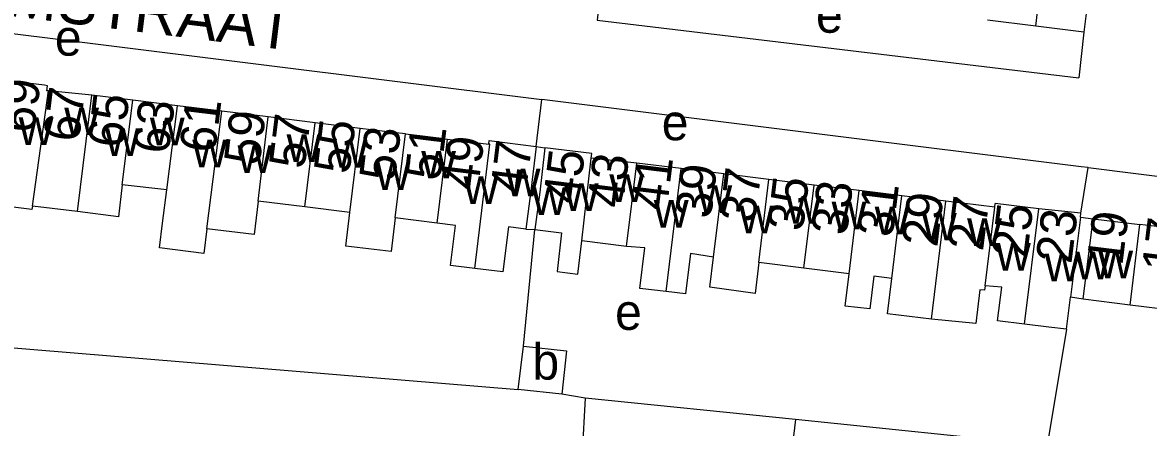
# Model space of a CAD drawing. Extents: x 157569 to 159501, y 382907 to 384670.
# Drawn here: x 158378.5 to 158503.7, y 383217.2 to 383262.2 of the extents above; entities that cross this region are included whole.
import ezdxf

# ---------------------------------------------------------------- set-up
doc = ezdxf.new("R2010")
doc.units = 0
for name, color, linetype in [('BLT_Basislijn', 7, 'Continuous'), ('BLT_Bebouwing', 7, 'Continuous'), ('BLT_Centroide', 7, 'Continuous'), ('BLT_Huisnummer', 7, 'Continuous'), ('BLT_Huisnummer_ tussenligend', 7, 'Continuous'), ('BLT_Onderdoorgang_en_onderverdeling', 7, 'Continuous'), ('BLT_Onderverdeling_panden', 7, 'Continuous'), ('BLT_Straatnaam', 7, 'Continuous')]:
    doc.layers.add(name, color=color, linetype=linetype)

msp = doc.modelspace()

# ---------------------------------------------------------------- linework, layer by layer
at = {"layer": 'BLT_Basislijn'}
for p, q in [((158496.49, 383261.17), (158495.91, 383256.08)), ((158435.58, 383248.43), (158436.22, 383253.68)), ((158496.15, 383241.01), (158496.96, 383246.09)), ((158434.19, 383226.22), (158435.43, 383239.19)), ((158494.57, 383228.1), (158492.39, 383215.18)), ((158367.29, 383226.88), (158433.59, 383221.41)), ((158441.03, 383220.43), (158438.43, 383220.88)), ((158441.03, 383220.43), (158439.9, 383199.74)), ((158464.44, 383218.06), (158441.03, 383220.43)), ((158492.39, 383215.18), (158464.44, 383218.06))]:
    msp.add_line(p, q, dxfattribs=at)
for points in [[(158442.95, 383267.73), (158442.38, 383262.5), (158495.91, 383256.08)], [(158339.59, 383265.74), (158436.22, 383253.68)], [(158496.96, 383246.09), (158496.17, 383246.19), (158436.22, 383253.68)], [(158496.96, 383246.09), (158554.1, 383238.91), (158555.85, 383237.47)], [(158464.44, 383218.06), (158463.94, 383214.05), (158463.22, 383193.67)]]:
    msp.add_lwpolyline(points, dxfattribs=at)
at = {"layer": 'BLT_Bebouwing'}
for p, q in [((158497.58, 383270.14), (158496.49, 383261.17)), ((158491.14, 383261.83), (158485.78, 383262.48)), ((158496.49, 383261.17), (158491.14, 383261.83)), ((158380.92, 383255.24), (158376.31, 383255.8)), ((158386.19, 383254.14), (158381.36, 383254.61)), ((158390.73, 383253.58), (158386.19, 383254.14)), ((158395.72, 383252.96), (158390.73, 383253.58)), ((158400.65, 383252.35), (158395.72, 383252.96)), ((158405.79, 383251.72), (158400.65, 383252.35)), ((158411.01, 383251.07), (158405.79, 383251.72)), ((158416.03, 383250.45), (158411.01, 383251.07)), ((158421.06, 383249.83), (158425.72, 383249.26)), ((158425.72, 383249.26), (158430.33, 383248.69)), ((158435.58, 383248.43), (158436.55, 383248.3)), ((158446.78, 383246.57), (158441.7, 383247.15)), ((158451.7, 383245.97), (158446.78, 383246.57)), ((158456.45, 383245.39), (158451.7, 383245.97)), ((158461.47, 383244.77), (158456.45, 383245.39)), ((158394.53, 383243.6), (158389.57, 383244.18)), ((158466.49, 383244.15), (158461.47, 383244.77)), ((158471.51, 383243.54), (158466.49, 383244.15)), ((158476.25, 383242.93), (158471.51, 383243.54)), ((158481.13, 383242.34), (158476.25, 383242.93)), ((158384.6, 383241.19), (158379.58, 383241.8)), ((158409.86, 383241.72), (158404.67, 383242.36)), ((158414.89, 383241.11), (158409.86, 383241.72)), ((158486.58, 383241.69), (158481.13, 383242.34)), ((158486.58, 383241.69), (158486.63, 383242.11)), ((158491.47, 383241.52), (158486.63, 383242.11)), ((158496.15, 383241.01), (158491.47, 383241.52)), ((158424.58, 383239.92), (158419.91, 383240.49)), ((158496.1, 383240.57), (158496.15, 383241.01)), ((158497.52, 383240.39), (158502.71, 383239.76)), ((158434.45, 383239.25), (158435.43, 383239.19)), ((158508.37, 383239.07), (158502.71, 383239.76)), ((158465.36, 383234.9), (158460.33, 383235.52)), ((158470.38, 383234.29), (158465.36, 383234.9)), ((158494.57, 383228.1), (158495.01, 383231.68)), ((158501.62, 383230.8), (158496.42, 383231.44)), ((158507.02, 383230.14), (158501.62, 383230.8)), ((158433.59, 383221.41), (158434.19, 383226.22)), ((158438.43, 383220.88), (158433.59, 383221.41))]:
    msp.add_line(p, q, dxfattribs=at)
for points in [[(158381.36, 383254.61), (158381.19, 383254.63), (158381.26, 383255.2), (158380.92, 383255.24)], [(158421.06, 383249.83), (158419.68, 383250), (158416.03, 383250.45)], [(158430.33, 383248.69), (158430.37, 383249.1), (158435.58, 383248.43)], [(158441.7, 383247.15), (158441.76, 383247.66), (158436.55, 383248.3)], [(158379.58, 383241.8), (158379.53, 383241.43), (158374.76, 383242.01), (158375.25, 383246.36)], [(158389.57, 383244.18), (158389.14, 383240.63), (158384.6, 383241.19)], [(158398.98, 383239.28), (158398.63, 383236.53), (158393.71, 383237.16), (158394.06, 383239.89), (158394.53, 383243.6)], [(158404.67, 383242.36), (158404.22, 383238.64), (158398.98, 383239.28)], [(158419.91, 383240.49), (158419.45, 383236.74), (158414.42, 383237.36), (158414.89, 383241.11)], [(158428.77, 383234.87), (158426.07, 383235.2), (158426.61, 383239.63), (158424.58, 383239.92)], [(158496.1, 383240.57), (158497.52, 383240.39)], [(158434.45, 383239.25), (158432.51, 383239.49), (158431.9, 383234.49), (158428.77, 383234.87)], [(158435.43, 383239.19), (158438.42, 383238.82), (158437.92, 383234.53), (158440.24, 383234.25), (158440.68, 383237.93)], [(158445.65, 383237.32), (158440.68, 383237.93)], [(158450.03, 383232.3), (158447.11, 383232.65), (158447.67, 383237.15), (158445.65, 383237.32)], [(158455.31, 383236.14), (158452.73, 383236.52), (158452.18, 383232.03), (158450.03, 383232.3)], [(158460.33, 383235.52), (158459.94, 383232.1), (158454.88, 383232.78), (158455.31, 383236.14)], [(158475.13, 383233.77), (158473.13, 383234.02), (158472.68, 383230.39), (158469.94, 383230.69), (158470.38, 383234.29)], [(158479.53, 383229.22), (158474.65, 383229.81), (158475.13, 383233.77)], [(158485.5, 383232.95), (158485.44, 383232.44), (158484.92, 383232.49), (158484.46, 383228.73), (158479.53, 383229.22)], [(158489.89, 383228.67), (158486.89, 383229.04), (158487.35, 383232.79), (158485.5, 383232.95)], [(158496.42, 383231.44), (158495.01, 383231.68)], [(158494.57, 383228.1), (158492.58, 383228.34), (158489.89, 383228.67)], [(158434.19, 383226.22), (158438.96, 383225.7), (158438.43, 383220.88)]]:
    msp.add_lwpolyline(points, dxfattribs=at)
at = {"layer": 'BLT_Onderdoorgang_en_onderverdeling'}
msp.add_line((158496.42, 383231.44), (158497.52, 383240.39), dxfattribs=at)
for points in [[(158435.58, 383248.43), (158435.01, 383243.49), (158434.45, 383239.25)], [(158436.55, 383248.3), (158435.98, 383243.37), (158435.43, 383239.19)], [(158496.1, 383240.57), (158495.01, 383231.68)]]:
    msp.add_lwpolyline(points, dxfattribs=at)
at = {"layer": 'BLT_Onderverdeling_panden'}
for p, q in [((158491.14, 383261.83), (158492.23, 383270.8)), ((158379.58, 383241.8), (158381.36, 383254.61)), ((158384.6, 383241.19), (158386.19, 383254.14)), ((158389.57, 383244.18), (158390.73, 383253.58)), ((158394.53, 383243.6), (158395.72, 383252.96)), ((158398.98, 383239.28), (158400.65, 383252.35)), ((158404.67, 383242.36), (158405.79, 383251.72)), ((158409.86, 383241.72), (158411.01, 383251.07)), ((158414.89, 383241.11), (158416.03, 383250.45)), ((158419.91, 383240.49), (158421.06, 383249.83)), ((158424.58, 383239.92), (158425.72, 383249.26)), ((158440.68, 383237.93), (158441.7, 383247.15)), ((158445.65, 383237.32), (158446.78, 383246.57)), ((158450.03, 383232.3), (158451.7, 383245.97)), ((158455.31, 383236.14), (158456.45, 383245.39)), ((158460.33, 383235.52), (158461.47, 383244.77)), ((158465.36, 383234.9), (158466.49, 383244.15)), ((158470.38, 383234.29), (158471.51, 383243.54)), ((158475.13, 383233.77), (158476.25, 383242.93)), ((158479.53, 383229.22), (158481.13, 383242.34)), ((158485.5, 383232.95), (158486.58, 383241.69)), ((158489.89, 383228.67), (158491.47, 383241.52)), ((158501.62, 383230.8), (158502.71, 383239.76))]:
    msp.add_line(p, q, dxfattribs=at)
msp.add_lwpolyline([(158428.77, 383234.87), (158430.45, 383248.68), (158430.33, 383248.69)], dxfattribs=at)

# ---------------------------------------------------------------- texts
at = {"layer": 'BLT_Centroide'}
for s, p in [('e', (158466.7, 383261.09)), ('e', (158382.08, 383258.54)), ('w', (158383.12, 383249.7)), ('w', (158378.06, 383248.59)), ('w', (158392.64, 383248.58)), ('e', (158449.55, 383249.13)), ('w', (158387.66, 383247.39)), ('w', (158397.36, 383246.11)), ('w', (158407.84, 383246.72)), ('w', (158412.95, 383246.09)), ('w', (158402.39, 383245.5)), ('w', (158422.81, 383244.88)), ('w', (158417.73, 383243.59)), ('w', (158427.52, 383242.03)), ('w', (158432.19, 383242.88)), ('w', (158443.73, 383242.25)), ('w', (158435.12, 383240.82)), ('w', (158438.67, 383241.27)), ('w', (158453.52, 383241.05)), ('w', (158448.67, 383239.41)), ('w', (158463.41, 383239.84)), ('w', (158458.17, 383238.77)), ('w', (158468.44, 383239.22)), ('w', (158473.23, 383238.66)), ('w', (158478.48, 383237.98)), ('w', (158483.5, 383237.38)), ('w', (158486.71, 383234.62)), ('w', (158492.13, 383233.44)), ('w', (158495.54, 383233.65)), ('w', (158498.09, 383233.77)), ('e', (158444.36, 383228.04)), ('b', (158435.17, 383222.51))]:
    msp.add_text(s, height=4, dxfattribs=at).set_placement(p)
at = {"layer": 'BLT_Huisnummer'}
for s, rotation, p in [('67', 82.9882, (158384.73, 383248.84)), ('63', 82.9882, (158394.71, 383247.5)), ('59', 82.9882, (158404.82, 383246.27)), ('55', 82.9882, (158414.81, 383245.28)), ('51', 82.9882, (158424.91, 383244.59)), ('47', 82.9882, (158434.42, 383242.94)), ('45', 82.9882, (158440.3, 383241.95)), ('41', 83.0051, (158450.1, 383241.2)), ('37', 83.0051, (158459.92, 383239.88)), ('33', 83.0051, (158470.11, 383238.46)), ('29', 83.0051, (158480.18, 383237.16)), ('25', 83.0051, (158490.15, 383235.94)), ('19', 83.0135, (158500.75, 383235.08))]:
    msp.add_text(s, height=4, rotation=rotation, dxfattribs=at).set_placement(p)
at = {"layer": 'BLT_Huisnummer_ tussenligend'}
for s, rotation, p in [('69', 82.9882, (158379.78, 383249.82)), ('65', 82.9882, (158389.66, 383248.17)), ('61', 82.9882, (158399.88, 383247.61)), ('57', 82.9882, (158409.82, 383245.86)), ('53', 82.9882, (158419.86, 383244.48)), ('49', 82.9882, (158429.11, 383243.43)), ('43', 82.9891, (158445.21, 383241.5)), ('39', 83.0051, (158455, 383240.32)), ('35', 83.0051, (158465.23, 383238.92)), ('31', 83.0051, (158475.21, 383238.24)), ('27', 83.0051, (158485.26, 383236.72)), ('23', 83.0051, (158495.09, 383235.31)), ('17', 83.0285, (158506.87, 383234.32))]:
    msp.add_text(s, height=4, rotation=rotation, dxfattribs=at).set_placement(p)
at = {"layer": 'BLT_Straatnaam'}
msp.add_text('BERGEN OP ZOOMSTRAAT', height=5, rotation=352.9387, dxfattribs=at).set_placement((158320.99, 383269.91))

doc.saveas('drawing.dxf')
